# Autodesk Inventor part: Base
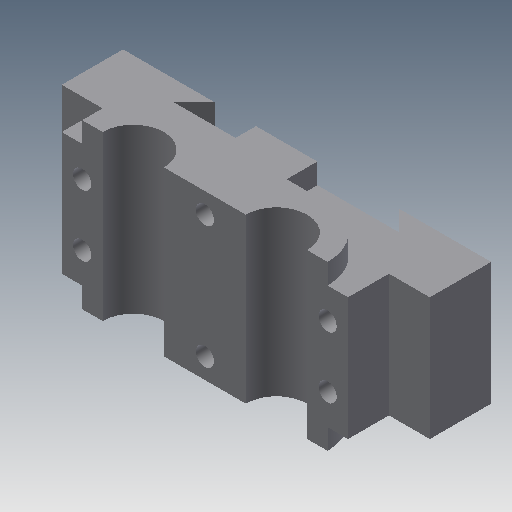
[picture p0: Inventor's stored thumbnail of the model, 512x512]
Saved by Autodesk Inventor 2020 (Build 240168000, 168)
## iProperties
Created: 2002-02
Part Number: Base
Document SubType Name: Modeling
Designer: ***
Density: 1 g/cm^3
Material: Generic
Appearance: Default
Control State: 0
Master: False
Checked Out: False
Shininess: 77.0
Length Units: 11269
Angle Units: 11279
Time Units: 11290
Mass Units: 11283
Length Display Precision: 3
Angle Display Precision: 2
Density: 0.0
Volumn: 0.0
Area: 0.0
PropertySet Name: Model Information
Author: ***
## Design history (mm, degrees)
sketch "Sketch2"
  geometry: L1 (-10.066, -1.263)-(24.934, -1.263); L2 (37.434, 11.237)-(32.434, 11.237); L3 (17.434, 11.237)-(-2.566, 11.237); L4 (-17.566, 11.237)-(-22.566, 11.237); A1 r 12.5 centre (-10.066, 11.237) between (-22.566, 11.237) and (-10.066, -1.263); A2 r 12.5 centre (24.934, 11.237) between (24.934, -1.263) and (37.434, 11.237); A3 r 7.5 centre (24.934, 11.237) between (17.434, 11.237) and (32.434, 11.237); A4 r 7.5 centre (-10.066, 11.237) between (-17.566, 11.237) and (-2.566, 11.237)
  constraints: 8 end point, 8 point on circle, 4 centre point, 3 horizontal, 3 parallel, 2 coincident, 2 equal radius, 2 tangent
  dimensions: "d0" = 12.5 radius of A1; "d1" = 7.5 radius of A4; "d2" = 35 distance of A1.centre A2.centre; "d3" = 12.5 distance between parallel lines of L3 L1
extrude "Extrusion1" new body sketch "Sketch2" stored distance "d4" = 40; taper "d5" = 0 deg
sketch "Sketch4"
  geometry: L1 (-27.566, 1.237)-(-37.566, 1.237); L2 (-37.566, 1.237)-(-37.566, -13.763); L3 (-37.566, -13.763)-(-15.066, -13.763); L4 (-15.066, -13.763)-(-20.066, -8.763); L5 (-20.066, -8.763)-(34.934, -8.763); L6 (34.934, -8.763)-(29.934, -13.763); L7 (29.934, -13.763)-(52.434, -13.763); L8 (52.434, -13.763)-(52.434, 1.237); L9 (52.434, 1.237)-(42.434, 1.237); L10 (24.934, -1.263)-(-10.066, -1.263); L11 (-17.566, 11.237)-(-22.566, 11.237) reference; L12 (37.434, 11.237)-(32.434, 11.237) reference; L13 (-22.566, 11.237)-(-27.566, 11.237); L14 (-27.566, 11.237)-(-27.566, 1.237); L15 (37.434, 11.237)-(42.434, 11.237); L16 (42.434, 11.237)-(42.434, 1.237); A1 r 12.5 centre (24.934, 11.237) between (24.934, -1.263) and (37.434, 11.237); A2 r 12.5 centre (-10.066, 11.237) between (-22.566, 11.237) and (-10.066, -1.263); A3 r 12.5 centre (24.934, 11.237) between (24.934, -1.263) and (37.434, 11.237) reference; A4 r 12.5 centre (-10.066, 11.237) between (-22.566, 11.237) and (-10.066, -1.263) reference
  constraints: 28 end point, 6 perpendicular, 5 equal length, 4 concentric, 4 parallel, 4 point on circle, 2 centre point, 2 collinear, 1 tangent
  dimensions: "d12" = 15 distance of L1.end L2.end; "d13" = 25 distance from line of L3 L11.end; "d14" = 90 distance between parallel lines of L2 L8; "d15" = 5 distance between parallel lines of L5 L7; "d16" = 22.5 distance of L2.end L3.end; "d24" = 5 distance of L12.start L15.end; "d25" = 15 distance from line of L8 L12.start
extrude "Extrusion3" join sketch "Sketch4" stored distance "d17" = 30; taper "d18" = 0 deg
sketch "Sketch5"
  geometry: L1 (-14.934, -1.263)-(0.066, -1.263); L2 (0.066, -1.263)-(0.066, -8.763); L3 (0.066, -8.763)-(-14.934, -8.763); L4 (-14.934, -8.763)-(-14.934, -1.263); L5 (10.066, -1.263)-(-24.934, -1.263) reference; 1 further point
  constraints: 8 end point, 2 parallel, 1 collinear, 1 horizontal, 1 perpendicular
  dimensions: "d19" = 7.5 distance of L1.end L2.end; "d20" = 15 distance of L2.end L3.end; "d21" = 15 distance from line of point (-29.934, -13.763) L4
extrude "Extrusion4" join sketch "Sketch5" distance "d22" = 40; taper "d23" = 0 deg
sketch "Sketch6"
  geometry: L1 (-5, -35)-(0, -35) reference; L2 (-5, -35)-(-5, -5) reference; 1 further point
  dimensions: "d26" = 7.5 distance from line of L1 point (0, -27.5); "d27" = 5 distance from line of L2 point (0, -27.5)
hole "Hole1" sketch "Sketch6" at (0, -27.5) diameter "d28" = 4.5; stored, may be unused: countersink angle "d32" = 82 deg, drill point angle "d34" = 0 deg; dims "d29" = 6, "d30" = 4, "d31" = 2, "d33" = 15
pattern_linear "Rectangular Pattern1" dims "d37" = 60, "d40" = 15
sketch "Sketch7"
  geometry: L1 (-20, -40)-(-20, -35) reference; L2 (0, -40)-(20, -40) reference; 1 further point
  dimensions: "d41" = 30 distance from line of L1 point (10, -35); "d42" = 5 distance from line of L2 point (10, -35)
hole "Hole2" sketch "Sketch7" at (10, -35) diameter "d43" = 4.5; stored, may be unused: countersink angle "d47" = 82 deg, drill point angle "d49" = 0 deg; dims "d44" = 6, "d45" = 4, "d46" = 2, "d48" = 15
pattern_linear "Rectangular Pattern2" dims "d52" = 30
body "Solid1"
